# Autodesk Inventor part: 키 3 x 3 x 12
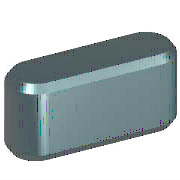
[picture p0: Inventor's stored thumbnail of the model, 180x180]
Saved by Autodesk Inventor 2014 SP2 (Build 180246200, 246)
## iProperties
Created: 2012-02
Part Number: 키 3 x 3 x 12
Material: 강철, 연강
Description: 키 및 해당 키홈
Document SubType Name: Modeling
Standard: KS B 1311
Designer: mduedu
Standards Organization: KS
Language: ko-KR
Size Designation: 3 x 3 x 12
Categories: <MemberInstance><Categories><Category DisplayName="샤프트 부품" InternalName="7f7aeb1f-a693-4053-b835-cee3144e0d98" Mnemonic="SHFT"><Category DisplayName="키" Interna
Density: 1 g/cm^3
Appearance: 강철
IsCustomPart: 1
Author: mduedu
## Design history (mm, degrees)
workplane "Work Plane1"
workplane "Work Plane2"
sketch "스케치1"
  geometry: L1 (1.5, 1.5)-(10.5, 1.5); L2 (10.5, -1.5)-(1.5, -1.5); L3 (0, 9.4)-(0, -7.4) reference; L4 (-5, 0)-(30, 0) reference; L5 (12, 0)-(12, 7); A1 r 1.5 centre (1.5, 0) between (1.5, 1.5) and (1.5, -1.5); A2 r 1.5 centre (10.5, 0) between (10.5, -1.5) and (10.5, 1.5)
  constraints: 6 end point, 5 point on circle, 4 tangent, 3 point on line, 2 centre point, 1 horizontal, 1 parallel, 1 perpendicular
  dimensions: "d0" = 1.5 radius of A1 (= 0.5 x PB); "d13" = 1.5 radius of A2 (= 0.5 x PB); "d14" = 12 distance between parallel lines of L5 L3 (= NLG)
extrude "본체1" new body sketch "스케치1" taper "d3" = 0 deg; stored distance "d4" = 10
workplane "Work Plane3"
body "Solid1"
chamfer "모따기1" distance "d8" = 0.25 (= PHH); stored, may be unused: second distance "d9" = 0.25 (= PHH), angle "d15" = 45 deg
other parameters: "d1" = -1.8 (= -PNT), "d2" = 1.2 (= PH - PNT), "NLG" = 12 [user parameter; used in 3 equation terms], "PB" = 3 [user parameter; used in 2 equation terms], "PNT" = 1.8 [user parameter; used in 2 equation terms], "PH" = 3 [user parameter; used in 1 equation term], "PHH" = 0.25 [user parameter; used in 2 equation terms], "d10" = 0, "d16" = 0, "d17" = 0, "d18" = 0, "WDMIN" = 8 [user parameter], "PLB2" = 12 (= NLG) [user parameter], "PLB1" = 12 (= NLG) [user parameter], "RR" = 0.08 [user parameter], "PUEB" = 1.4 [user parameter]
